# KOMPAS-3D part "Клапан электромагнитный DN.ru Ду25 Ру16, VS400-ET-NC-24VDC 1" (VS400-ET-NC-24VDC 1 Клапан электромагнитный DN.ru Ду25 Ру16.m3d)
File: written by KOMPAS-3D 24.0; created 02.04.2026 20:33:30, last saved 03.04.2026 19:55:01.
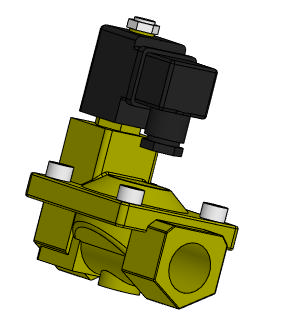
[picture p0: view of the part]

Document properties: Автор: artio; Полное имя файла: C:\Users\artio\OneDrive\Рабочий стол\Клапан электромагнитный DN.ru\VS400-ET-NC\VS400-ET-NC-24VDC 1 Клапан электромагнитный DN.ru Ду25 Ру16.m3d

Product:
- Body: Тело 1  | qty 1
    Масса: 1.76797
- Part/product: Клапан электромагнитный DN.ru Ду25 Ру16  | designation VS400-ET-NC-24VDC 1
    Масса: 1.524
    Раздел спецификации: Прочие изделия
    Примечание: D130-04721
    additional columns: ef56311e-7521-43dc-8291-0e6108b3d81d; VS400-ET-NC-220VAC 1; artio; c; Шероховатость не задана; Да

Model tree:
1. Операция без истории:1

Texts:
  VS400-ET-NC-24VDC 1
